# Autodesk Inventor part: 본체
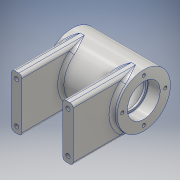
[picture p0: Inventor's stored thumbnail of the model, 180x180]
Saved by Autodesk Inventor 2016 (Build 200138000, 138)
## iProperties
Created: 2020-07
Part Number: 본체
Material: 알루미늄 6061
Document SubType Name: Modeling
Designer: user
Density: 2.7 g/cm^3
Appearance: 알루미늄 - 평지
Author: user
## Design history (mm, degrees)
sketch "스케치8"
  geometry: L1 (0, 26)-(-64, 26); L2 (-64, 26)-(-64, -26); L3 (-64, -26)-(0, -26); A1 r 26 centre (0, 0) between (0, 26) and (0, -26); 2 further points
  constraints: 6 end point, 2 coincident, 2 point on circle, 1 centre point, 1 horizontal, 1 perpendicular, 1 tangent, 1 vertical alignment, 2 other
  dimensions: "d27" = 52 diameter of A1; "d28" = 64 distance of L1.start L1.end; "d29" = 52 distance of L1.end L2.end; "d30" = 64 distance of L2.end L3.end
extrude "돌출2" new body sketch "스케치8" distance "d31" = 10; taper "d32" = 0 deg
sketch "스케치9"
  geometry: A1 r 26 centre (0, 0) between (0, 26) and (0, -26) reference; 2 further points
  constraints: 1 coincident, 1 vertical alignment, 2 other
extrude "돌출3" join sketch "스케치9" distance "d33" = 5; taper "d34" = 0 deg
sketch "스케치10"
  geometry: C1 r 26 at (0, 0); 1 further point
  constraints: 1 centre point, 1 coincident
extrude "돌출4" join sketch "스케치10" distance "d35" = 50; taper "d36" = 0 deg
sketch "스케치11"
  geometry: L1 (26, -64)-(26, 0) reference; L2 (26, 0)-(26, -64); L3 (26, -64)-(-26, -64); L4 (-26, -64)-(-26, 0); A1 r 26 centre (0, 0) between (-26, 0) and (26, 0); 1 further point
  constraints: 6 end point, 2 point on circle, 1 centre point, 1 coincident, 1 collinear, 1 perpendicular
  dimensions: "d40" = 64 distance of L1.end L1.start (derived); "d41" = 52 distance of L1.start L3.end; "d42" = 64 distance of L3.end L4.end (derived)
extrude "돌출5" join sketch "스케치11" distance "d43" = 10; taper "d44" = 0 deg
sketch "스케치12"
  geometry: C1 r 26 at (0, 0); 1 further point
  constraints: 1 centre point, 1 coincident
extrude "돌출6" join sketch "스케치12" distance "d45" = 15; taper "d46" = 0 deg
sketch "스케치13"
  geometry: L1 (-5, 26)-(-5, -26) reference; L2 (-5, 0)-(65, 0); L3 (-5, 0)-(7, 0); L4 (7, 0)-(7, 16); L5 (7, 16)-(-5, 16); L6 (-5, 16)-(-5, 0); L7 (7, 0)-(9, 0); L8 (9, 0)-(9, 14); L9 (9, 14)-(7, 14); L10 (7, 14)-(7, 0); L11 (9, 0)-(51.31, 0); L12 (51.31, 0)-(53, 0); L13 (53, 0)-(65, 0); L14 (9, 0)-(51, 0); L15 (51, 0)-(51, 21); L16 (51, 21)-(9, 21); L17 (9, 21)-(9, 0); L18 (51, 0)-(53, 0); L19 (53, 0)-(53, 14); L20 (53, 14)-(51, 14); L21 (51, 14)-(51, 0); L22 (50, -26)-(50, 0) reference; L23 (65, -26)-(65, 26) reference; L24 (50, 0)-(65, 0); L25 (53, 0)-(65, 0); L26 (65, 0)-(65, 16); L27 (65, 16)-(53, 16); L28 (53, 16)-(53, 0); 1 further point
  constraints: 50 end point, 10 parallel, 9 horizontal, 5 perpendicular, 1 midpoint, 1 point on line
  dimensions: "d48" = 32 diameter of L5 L2; "d49" = 28 diameter of L9 L2; "d56" = 2 distance between parallel lines of L8 L10; "d57" = 12 distance between parallel lines of L1 L4; "d58" = 12 distance between parallel lines of L26 L19; "d59" = 42 distance between parallel lines of L17 L15; "d73" = 42 diameter of L16 L2
revolve "회전2" sketch "스케치13" stored, may be unused: angle "d60" = 90 deg
sketch "스케치17"
  geometry: A1 r 21 centre (0, 0) between (0, 21) and (21, 0); 3 further points
  constraints: 4 point on circle, 1 centre point, 1 coincident
  dimensions: "d65" = 42 diameter of A1
hole "구멍1" sketch "스케치17" at (0, 21), (21, 0), (0, -21), (-21, 0) diameter "d66" = 3.242; stored, may be unused: countersink angle "d70" = 90 deg, drill point angle "d72" = 118 deg; dims "d67" = 8, "d68" = 4, "d69" = 2, "d71" = 10
fillet "모깎기1" dims "d77" = 3
sketch "스케치22"
  geometry: 1 further point
sketch "스케치23"
  geometry: 8 further points
  constraints: 2 coincident
hole "구멍2" sketch "스케치23" at (0, 21), (-21, 0), (21, 0), (0, -21) diameter "d79" = 3.242; stored, may be unused: countersink angle "d83" = 90 deg, drill point angle "d85" = 118 deg; dims "d80" = 8, "d81" = 4, "d82" = 2, "d84" = 10
sketch "스케치24"
  geometry: L1 (-50, 46)-(-50, 0) reference; L2 (-45, 3.621)-(-45, 0.379) reference; L3 (5, 0.379)-(5, 3.621) reference; 5 further points
hole "구멍3" sketch "스케치24" at (-45, 43), (-45, 3), (5, 3), (5, 43) diameter "d93" = 4.134; stored, may be unused: countersink angle "d97" = 90 deg, drill point angle "d99" = 118 deg; dims "d94" = 10, "d95" = 4, "d96" = 2, "d98" = 10
sketch "스케치25"
  geometry: L1 (5, 1.621)-(5, -1.621) reference; C1 r 5 at (-30, 0); 1 further point
  constraints: 1 centre point
  dimensions: "d101" = 10 diameter of C1
extrude "돌출8" join sketch "스케치25" distance "d102" = 29; taper "d103" = 0 deg
sketch "스케치26"
  geometry: C1 r 14 at (0, 0); 1 further point
  constraints: 1 centre point, 1 coincident
extrude "돌출9" cut sketch "스케치26" distance "d104" = 100; taper "d105" = 0 deg
node "스케치27"
sketch "스케치28"
  geometry: C1 r 21 at (0, 0); 1 further point
  constraints: 1 centre point, 1 coincident
  dimensions: "d106" = 42 diameter of C1
extrude "돌출10" cut sketch "스케치28" distance "d107" = 42; taper "d108" = 0 deg
sketch "스케치29"
  geometry: 2 further points
hole "구멍4" sketch "스케치29" at (0, 0) diameter "d109" = 5.188; stored, may be unused: countersink angle "d113" = 90 deg, drill point angle "d115" = 118 deg; dims "d110" = 16, "d111" = 4, "d112" = 2, "d114" = 20
fillet "모깎기2" dims "d116" = 0.3
sketch "스케치30"
  geometry: 1 further point
fillet "모깎기3" dims "d119" = 2
node "솔리드2"
